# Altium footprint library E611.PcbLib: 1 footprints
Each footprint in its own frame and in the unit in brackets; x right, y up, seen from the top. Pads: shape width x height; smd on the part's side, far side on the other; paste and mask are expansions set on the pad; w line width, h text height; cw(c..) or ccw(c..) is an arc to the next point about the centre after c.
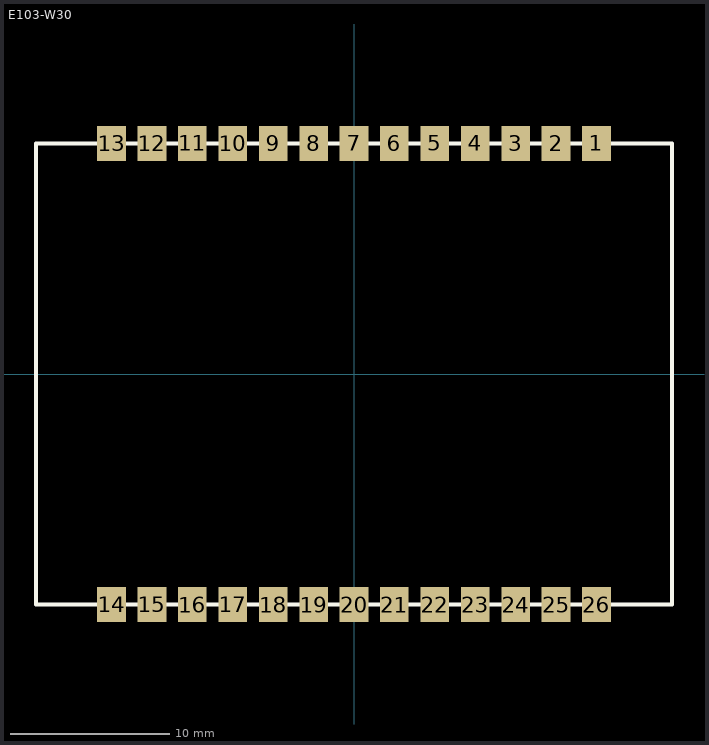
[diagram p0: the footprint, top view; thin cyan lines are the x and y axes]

## E103-W30 [mm]
pads (26):
  rect 1.8x2.2 smd mask+0: 1(15.24,14.5) 2(12.7,14.5) 3(10.16,14.5) 4(7.62,14.5) 5(5.08,14.5) 6(2.54,14.5) 7(0,14.5) 8(-2.54,14.5) 9(-5.08,14.5) 10(-7.62,14.5) 11(-10.16,14.5) 12(-12.7,14.5) 13(-15.24,14.5) 14(-15.24,-14.5) 15(-12.7,-14.5) 16(-10.16,-14.5) 17(-7.62,-14.5) 18(-5.08,-14.5) 19(-2.54,-14.5) 20(0,-14.5) 21(2.54,-14.5) 22(5.08,-14.5) 23(7.62,-14.5) 24(10.16,-14.5) 25(12.7,-14.5) 26(15.24,-14.5)
Top Overlay:
  lines w0.254: -20,-14.5 -20,14.5 20,14.5 20,-14.5 -20,-14.5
